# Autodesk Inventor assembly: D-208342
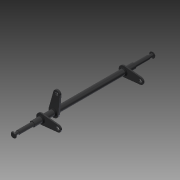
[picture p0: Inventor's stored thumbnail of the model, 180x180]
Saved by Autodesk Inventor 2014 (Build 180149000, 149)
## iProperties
Created: 2007-10
Part Number: D-208342
Document SubType Name: Weldment
Designer: TH
Weld Material: Welded Steel Mild (Black-Flat)
Mass: 602.959 g
Surface Area: 279.565 cm^2
Volume: 76.8088 cm^3
Density: 7.85013 g/cm^3
Description: FRONT PIVOT WELDMENT
Component Category: Lower Component
Author: TH
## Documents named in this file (4)
- C:\Users\iTools\Desktop\tutorial files\Automotive\2000\208342.iam
- C:\Users\iTools\Desktop\tutorial files\Automotive\2000\200987.ipt
- C:\Users\iTools\Desktop\tutorial files\Automotive\2000\201135.ipt
- C:\Users\iTools\Desktop\tutorial files\Automotive\2000\201099.ipt
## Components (4 placed, 3 different names)
1. 200987:1 — Mate:2, Flush:2, Mate:3, Angle:1, Mate:4, Mate:6
2. 201135:1 — Mate:2, Flush:2, Flush:3, Angle:1, Mate:5
3. 201135:2 — Mate:3, Flush:3
4. 201099:1 — Mate:4, Mate:5, Mate:6
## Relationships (8: Mate 5, Flush 2, Angle 1)
- Mate:2: 200987:1 ↔ 201135:1
- Flush:2: 200987:1 ↔ 201135:1
- Mate:3: 200987:1 ↔ 201135:2
- Flush:3: 201135:1 ↔ 201135:2
- Angle:1: 200987:1 ↔ 201135:1
- Mate:4: 200987:1 ↔ 201099:1
- Mate:5: 201135:1 ↔ 201099:1
- Mate:6: 200987:1 ↔ 201099:1
